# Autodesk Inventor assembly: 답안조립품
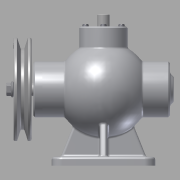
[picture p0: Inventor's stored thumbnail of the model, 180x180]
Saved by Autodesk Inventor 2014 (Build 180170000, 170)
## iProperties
Created: 2015-10
Part Number: 답안조립품
Document SubType Name: Assembly
Designer: youjin21
Author: youjin21
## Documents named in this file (19)
- C:\Users\youjin21\Desktop\451010V1001\답안조립품.iam
- C:\Users\youjin21\Desktop\451010V1001\본체.ipt
- C:\Users\youjin21\Desktop\451010V1001\뒤커버.ipt
- C:\Users\youjin21\Desktop\451010V1001\앞커버.ipt
- C:\Users\youjin21\Desktop\451010V1001\볼트 M4 x 16.ipt
- C:\Users\youjin21\Desktop\451010V1001\상부커버.ipt
- C:\Users\youjin21\Desktop\451010V1001\볼트 M 4 x 12.ipt
- C:\Users\youjin21\Desktop\451010V1001\베어링- 6202.ipt
- KS B 2023 - 6202 - 15 x 35 x 11 - 7.8.ipt
- C:\Users\youjin21\Desktop\451010V1001\부시.ipt
- C:\Users\youjin21\Desktop\451010V1001\편심축.ipt
- C:\Users\youjin21\Desktop\451010V1001\멈춤링- 15 x 1.ipt
- C:\Users\youjin21\Desktop\451010V1001\멈춤링- 35x1.6.ipt
- KS B 1336 - 35x1.6.ipt
- C:\Users\youjin21\Desktop\451010V1001\오일실 15 30 7.ipt
- C:\Users\youjin21\Desktop\451010V1001\키 4 x 4 x 12.ipt
- C:\Users\youjin21\Desktop\451010V1001\V-벨트풀리.ipt
- C:\Users\youjin21\Desktop\451010V1001\너트 M8.ipt
- C:\Users\youjin21\Desktop\451010V1001\슬라이드.ipt
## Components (16 placed, 5 different names)
1. KS B 2023 - 6202 - 15 x 35 x 11 - 7.8:1 — Mate:10, Mate:11, Mate:14, Mate:15, Angle:2
2. KS B 2023 - 6202 - 15 x 35 x 11 - 7.8:2 — Mate:12, Mate:13, Angle:1
3. KS B 1336 - 35x1.6:1 — Mate:20, Mate:21
4. V-벨트풀리:1 — Mate:27, Mate:28, Mate:29, Mate:30
5. ISO 4762 M4 x 16:1 — Insert:1
6. ISO 4762 M4 x 16:2
7. ISO 4762 M4 x 16:3
8. ISO 4762 M4 x 16:4
9. ISO 4762 M4 x 16:5 — Insert:2
10. ISO 4762 M4 x 16:6
11. ISO 4762 M4 x 16:7
12. ISO 4762 M4 x 16:8
13. KS B 1021 - 에 따름 ISO 1207 - 미터 A  M 4 x 12:1 — Insert:3
14. KS B 1021 - 에 따름 ISO 1207 - 미터 A  M 4 x 12:2
15. KS B 1021 - 에 따름 ISO 1207 - 미터 A  M 4 x 12:3
16. KS B 1021 - 에 따름 ISO 1207 - 미터 A  M 4 x 12:4
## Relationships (17: Mate 12, Insert 3, Angle 2)
- Insert:1: ISO 4762 M4 x 16:1
- Insert:2: ISO 4762 M4 x 16:5
- Insert:3: KS B 1021 - 에 따름 ISO 1207 - 미터 A  M 4 x 12:1
- Mate:10: KS B 2023 - 6202 - 15 x 35 x 11 - 7.8:1
- Mate:11: KS B 2023 - 6202 - 15 x 35 x 11 - 7.8:1
- Mate:12: KS B 2023 - 6202 - 15 x 35 x 11 - 7.8:2
- Mate:13: KS B 2023 - 6202 - 15 x 35 x 11 - 7.8:2
- Mate:14: KS B 2023 - 6202 - 15 x 35 x 11 - 7.8:1
- Mate:15: KS B 2023 - 6202 - 15 x 35 x 11 - 7.8:1
- Mate:20: KS B 1336 - 35x1.6:1
- Mate:21: KS B 1336 - 35x1.6:1
- Mate:27: V-벨트풀리:1
- Mate:28: V-벨트풀리:1
- Mate:29: V-벨트풀리:1
- Mate:30: V-벨트풀리:1
- Angle:1: KS B 2023 - 6202 - 15 x 35 x 11 - 7.8:2
- Angle:2: KS B 2023 - 6202 - 15 x 35 x 11 - 7.8:1
